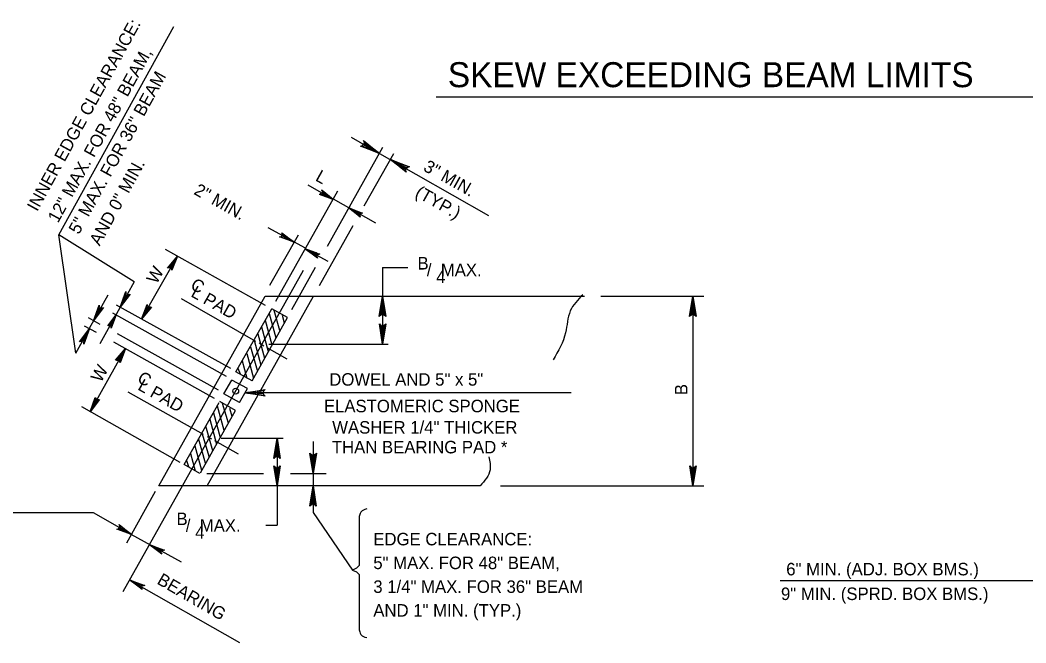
# Model space of a CAD drawing. Extents: x 639028 to 640031, y 298558 to 299746.
# Drawn here: x 639151 to 639392.4, y 298840.4 to 298989.8 of the extents above; entities that cross this region are included whole.
import ezdxf

# ---------------------------------------------------------------- set-up
doc = ezdxf.new("R2010")
doc.units = 0
doc.layers.add('1', color=7, linetype='Continuous')

msp = doc.modelspace()

# ---------------------------------------------------------------- linework, layer by layer
at = {"layer": '1'}
for p, q in [((639160.3, 298938.26), (639187.95, 298988.24)), ((639250.86, 298971.38), (639411.63, 298971.38)), ((639230.45, 298961.68), (639237.27, 298957.8)), ((639224.75, 298935.53), (639238.1, 298959.27)), ((639233.61, 298945.19), (639240.7, 298957.8)), ((639237.27, 298957.8), (639263.46, 298942.91)), ((639226.17, 298946.76), (639220.17, 298950.14)), ((639212.4, 298922.35), (639227.23, 298948.79)), ((639226.17, 298946.9), (639236.3, 298941.14)), ((639219.5, 298935.02), (639210.56, 298939.96)), ((639222.85, 298926.06), (639230.98, 298940.52)), ((639164.42, 298909.89), (639160.3, 298938.26)), ((639178.38, 298926.96), (639160.3, 298938.26)), ((639210.92, 298926.14), (639217.79, 298938.27)), ((639180.17, 298918.01), (639188.8, 298933.14)), ((639209.92, 298921.26), (639185.92, 298934.76)), ((639219.42, 298934.89), (639224.86, 298931.91)), ((639216.21, 298920.33), (639221.91, 298930.48)), ((639238, 298930.41), (639238, 298912.04)), ((639238, 298930.41), (639244.08, 298930.41)), ((639175.76, 298852.66), (639219.05, 298929.76)), ((639178.38, 298926.96), (639175.04, 298920.89)), ((639172.05, 298923.76), (639167.63, 298915.74)), ((639184.3, 298878.01), (639209.8, 298923.51)), ((639195.92, 298878.01), (639221.42, 298923.51)), ((639209.8, 298923.51), (639286.42, 298923.51)), ((639290.38, 298923.51), (639315.1, 298923.51)), ((639312.47, 298923.51), (639312.47, 298878.01)), ((639170.26, 298912.18), (639175.06, 298920.85)), ((639201.55, 298906.14), (639174.14, 298921.36)), ((639207.57, 298912.69), (639189.72, 298922.87)), ((639170.27, 298916.73), (639167.43, 298918.3)), ((639200.55, 298904.26), (639173.24, 298919.43)), ((639202.8, 298905.39), (639211.42, 298920.51)), ((639206.67, 298903.26), (639215.17, 298918.39)), ((639210.8, 298919.39), (639212.42, 298913.51)), ((639215.17, 298918.39), (639211.42, 298920.51)), ((639211.92, 298920.14), (639213.3, 298915.39)), ((639213.92, 298919.01), (639214.42, 298917.14)), ((639164.42, 298909.89), (639167.67, 298915.76)), ((639169.36, 298914.78), (639166.51, 298916.37)), ((639208.92, 298916.14), (639210.55, 298910.26)), ((639209.8, 298917.76), (639211.42, 298911.89)), ((639198.67, 298901.01), (639174.36, 298914.46)), ((639208.05, 298914.51), (639209.67, 298908.64)), ((639167.8, 298895.76), (639176.3, 298911.01)), ((639197.67, 298899.01), (639173.48, 298912.48)), ((639206.3, 298911.39), (639207.92, 298905.76)), ((639207.17, 298913.01), (639208.8, 298907.01)), ((639209.54, 298911.56), (639208.38, 298912.22)), ((639215.1, 298908.4), (639210.32, 298911.12)), ((639210.69, 298912.04), (639239.37, 298912.04)), ((639205.42, 298909.76), (639207.05, 298903.89)), ((639203.3, 298906.26), (639203.8, 298904.89)), ((639204.3, 298908.01), (639205.42, 298903.89)), ((639206.67, 298903.26), (639202.8, 298905.39)), ((639199.92, 298900.14), (639201.8, 298903.39)), ((639205.55, 298901.39), (639201.8, 298903.39)), ((639203.67, 298898.01), (639205.55, 298901.39)), ((639195.02, 298890.34), (639176.96, 298900.51)), ((639203.67, 298898.01), (639199.92, 298900.14)), ((639283.28, 298900.34), (639204.97, 298900.34)), ((639189.42, 298883.64), (639165.8, 298897.01)), ((639190.42, 298883.14), (639198.8, 298898.01)), ((639198.3, 298897.26), (639199.92, 298891.39)), ((639202.67, 298896.14), (639198.92, 298898.26)), ((639199.55, 298897.89), (639200.92, 298893.14)), ((639201.3, 298896.64), (639201.8, 298894.76)), ((639194.3, 298881.14), (639202.67, 298896.14)), ((639197.42, 298895.51), (639199.05, 298889.64)), ((639195.55, 298892.39), (639197.17, 298886.51)), ((639196.55, 298894.01), (639198.17, 298888.01)), ((639193.8, 298889.26), (639195.42, 298883.51)), ((639194.67, 298890.76), (639196.42, 298884.89)), ((639197.01, 298889.22), (639196.03, 298889.78)), ((639199.27, 298889.45), (639214.17, 298889.45)), ((639212.68, 298889.45), (639212.68, 298868.6)), ((639192.92, 298887.64), (639194.55, 298881.76)), ((639203.41, 298885.62), (639197.77, 298888.8)), ((639221.33, 298888.67), (639221.33, 298878.01)), ((639191.92, 298885.76), (639193.05, 298881.64)), ((639194.17, 298881.01), (639190.42, 298883.14)), ((639190.92, 298884.14), (639191.42, 298882.64)), ((639195.8, 298881.01), (639209.45, 298881.01)), ((639215.91, 298881.01), (639224.47, 298881.01)), ((639261.42, 298878.01), (639184.3, 298878.01)), ((639221.33, 298878.01), (639221.33, 298871.64)), ((639266.3, 298878.01), (639315.1, 298878.01)), ((639176.62, 298864.38), (639183.55, 298876.76)), ((639233.75, 298872.36), (639233.44, 298872.21)), ((639234.22, 298872.52), (639233.75, 298872.36)), ((639168.61, 298871.52), (639098.81, 298871.52)), ((639177.77, 298866.38), (639168.61, 298871.52)), ((639221.33, 298871.64), (639230.8, 298857.83)), ((639232.51, 298871.12), (639232.35, 298870.65)), ((639232.35, 298870.65), (639232.35, 298858.92)), ((639232.66, 298871.43), (639232.51, 298871.12)), ((639232.82, 298871.74), (639232.66, 298871.43)), ((639232.97, 298871.89), (639232.82, 298871.74)), ((639233.13, 298872.05), (639232.97, 298871.89)), ((639233.44, 298872.21), (639233.13, 298872.05)), ((639209.95, 298868.6), (639212.68, 298868.6)), ((639189.74, 298859.7), (639177.7, 298866.32)), ((639231.42, 298858.15), (639230.8, 298857.83)), ((639230.8, 298857.83), (639231.73, 298857.37)), ((639231.73, 298858.3), (639231.42, 298858.15)), ((639232.04, 298858.61), (639231.73, 298858.3)), ((639232.35, 298858.92), (639232.04, 298858.61)), ((639231.73, 298857.37), (639231.88, 298857.21)), ((639231.88, 298857.21), (639232.2, 298856.9)), ((639232.2, 298856.9), (639232.35, 298856.74)), ((639232.35, 298856.74), (639232.35, 298843.47)), ((639203.76, 298840.35), (639177.3, 298855.4)), ((639403.23, 298855.21), (639333.43, 298855.21)), ((639232.35, 298843.47), (639232.51, 298843.01)), ((639232.51, 298843.01), (639232.66, 298842.7)), ((639232.66, 298842.7), (639232.82, 298842.39)), ((639232.82, 298842.39), (639232.97, 298842.23)), ((639232.97, 298842.23), (639233.13, 298842.07)), ((639233.13, 298842.07), (639233.44, 298841.92)), ((639233.44, 298841.92), (639233.75, 298841.76)), ((639233.75, 298841.76), (639234.22, 298841.61))]:
    msp.add_line(p, q, dxfattribs=at)
for points in [[(639233.55, 298960.59), (639233.53, 298960.21), (639237.27, 298957.8), (639233.55, 298960.59), (639233.44, 298960.88), (639237.27, 298957.8), (639233.31, 298959.81), (639233, 298959.6), (639237.27, 298957.8), (639232.68, 298959.53), (639233, 298959.6)], [(639243.6, 298953.54), (639243.61, 298953.92), (639239.87, 298956.33), (639243.6, 298953.54), (639243.7, 298953.25), (639239.87, 298956.33), (639243.84, 298954.32), (639244.14, 298954.53), (639239.87, 298956.33), (639244.47, 298954.6), (639244.14, 298954.53)], [(639223.47, 298948.86), (639223.47, 298948.56), (639226.17, 298946.76), (639223.47, 298948.86), (639223.32, 298949.01), (639226.17, 298946.76), (639223.32, 298948.26), (639223.02, 298948.11), (639226.17, 298946.76), (639222.87, 298947.96), (639223.02, 298948.11)], [(639232.62, 298942.66), (639232.62, 298942.96), (639229.92, 298944.76), (639232.62, 298942.66), (639232.62, 298942.51), (639229.92, 298944.76), (639232.77, 298943.26), (639232.92, 298943.41), (639229.92, 298944.76), (639233.22, 298943.41), (639232.92, 298943.41)], [(639213.92, 298938.51), (639213.92, 298938.26), (639216.8, 298936.51), (639213.92, 298938.51), (639213.8, 298938.76), (639216.8, 298936.51), (639213.8, 298938.01), (639213.55, 298937.76), (639216.8, 298936.51), (639213.3, 298937.76), (639213.55, 298937.76)], [(639186.67, 298930.39), (639186.92, 298930.39), (639188.8, 298933.14), (639186.67, 298930.39), (639186.42, 298930.26), (639188.8, 298933.14), (639187.3, 298930.14), (639187.42, 298930.01), (639188.8, 298933.14), (639187.42, 298929.76), (639187.42, 298930.01)], [(639221.67, 298933.26), (639221.67, 298933.51), (639219.42, 298934.89), (639221.67, 298933.26), (639221.8, 298933.14), (639219.42, 298934.89), (639221.8, 298933.76), (639222.05, 298933.89), (639219.42, 298934.89), (639222.17, 298933.89), (639222.05, 298933.89)], [(639222.3, 298932.89), (639222.3, 298933.14), (639219.42, 298934.89), (639222.3, 298932.89), (639222.42, 298932.64), (639219.42, 298934.89), (639222.42, 298933.51), (639222.67, 298933.64), (639219.42, 298934.89), (639222.92, 298933.64), (639222.67, 298933.64)], [(639177.29, 298923.89), (639176.99, 298923.89), (639175.04, 298920.89), (639177.29, 298923.89), (639177.44, 298924.04), (639175.04, 298920.89), (639176.54, 298924.04), (639176.39, 298924.34), (639175.04, 298920.89), (639176.39, 298924.64), (639176.39, 298924.34)], [(639237.42, 298918.9), (639237.75, 298919.07), (639238, 298923.51), (639237.42, 298918.9), (639237.22, 298918.66), (639238, 298923.51), (639238.22, 298919.07), (639238.55, 298918.91), (639238, 298923.51), (639238.77, 298918.66), (639238.55, 298918.91)], [(639311.89, 298918.9), (639312.22, 298919.07), (639312.47, 298923.51), (639311.89, 298918.9), (639311.69, 298918.66), (639312.47, 298923.51), (639312.69, 298919.07), (639313.02, 298918.91), (639312.47, 298923.51), (639313.24, 298918.66), (639313.02, 298918.91)], [(639170.92, 298920.64), (639170.62, 298920.64), (639168.67, 298917.64), (639170.92, 298920.64), (639171.07, 298920.79), (639168.67, 298917.64), (639170.17, 298920.79), (639170.02, 298921.09), (639168.67, 298917.64), (639170.02, 298921.39), (639170.02, 298921.09)], [(639182.3, 298920.89), (639182.05, 298920.89), (639180.17, 298918.01), (639182.3, 298920.89), (639182.55, 298920.89), (639180.17, 298918.01), (639181.67, 298921.01), (639181.55, 298921.26), (639180.17, 298918.01), (639181.55, 298921.51), (639181.55, 298921.26)], [(639172.29, 298916.52), (639172.54, 298916.52), (639174.04, 298919.02), (639172.29, 298916.52), (639172.04, 298916.39), (639174.04, 298919.02), (639172.79, 298916.39), (639172.91, 298916.14), (639174.04, 298919.02), (639172.91, 298915.89), (639172.91, 298916.14)], [(639165.57, 298912.76), (639165.87, 298912.76), (639167.67, 298915.76), (639165.57, 298912.76), (639165.27, 298912.61), (639167.67, 298915.76), (639166.17, 298912.61), (639166.32, 298912.31), (639167.67, 298915.76), (639166.32, 298912.01), (639166.32, 298912.31)], [(639238.58, 298916.65), (639238.25, 298916.48), (639238, 298912.04), (639238.58, 298916.65), (639238.78, 298916.89), (639238, 298912.04), (639237.78, 298916.48), (639237.45, 298916.64), (639238, 298912.04), (639237.23, 298916.89), (639237.45, 298916.64)], [(639174.17, 298908.14), (639174.55, 298908.14), (639176.3, 298911.01), (639174.17, 298908.14), (639173.92, 298908.14), (639176.3, 298911.01), (639174.8, 298908.01), (639174.92, 298907.76), (639176.3, 298911.01), (639175.05, 298907.51), (639174.92, 298907.76)], [(639169.92, 298898.64), (639169.55, 298898.64), (639167.8, 298895.76), (639169.92, 298898.64), (639170.05, 298898.76), (639167.8, 298895.76), (639169.3, 298898.76), (639169.17, 298899.01), (639167.8, 298895.76), (639169.05, 298899.26), (639169.17, 298899.01)], [(639209.58, 298899.76), (639209.41, 298900.1), (639204.97, 298900.34), (639209.58, 298899.76), (639209.82, 298899.56), (639204.97, 298900.34), (639209.41, 298900.56), (639209.57, 298900.89), (639204.97, 298900.34), (639209.82, 298901.11), (639209.57, 298900.89)], [(639212.1, 298884.84), (639212.44, 298885.01), (639212.68, 298889.45), (639212.1, 298884.84), (639211.9, 298884.6), (639212.68, 298889.45), (639212.9, 298885.01), (639213.23, 298884.85), (639212.68, 298889.45), (639213.45, 298884.6), (639213.23, 298884.85)], [(639221.91, 298885.62), (639221.58, 298885.45), (639221.33, 298881.01), (639221.91, 298885.62), (639222.11, 298885.86), (639221.33, 298881.01), (639221.11, 298885.45), (639220.78, 298885.61), (639221.33, 298881.01), (639220.56, 298885.86), (639220.78, 298885.61)], [(639213.26, 298882.62), (639212.93, 298882.45), (639212.68, 298878.01), (639213.26, 298882.62), (639213.46, 298882.86), (639212.68, 298878.01), (639212.46, 298882.45), (639212.13, 298882.61), (639212.68, 298878.01), (639211.91, 298882.86), (639212.13, 298882.61)], [(639313.05, 298882.62), (639312.71, 298882.45), (639312.47, 298878.01), (639313.05, 298882.62), (639313.25, 298882.86), (639312.47, 298878.01), (639312.25, 298882.45), (639311.92, 298882.61), (639312.47, 298878.01), (639311.7, 298882.86), (639311.92, 298882.61)], [(639220.75, 298873.4), (639221.09, 298873.57), (639221.33, 298878.01), (639220.75, 298873.4), (639220.55, 298873.16), (639221.33, 298878.01), (639221.55, 298873.57), (639221.88, 298873.41), (639221.33, 298878.01), (639222.1, 298873.16), (639221.88, 298873.41)], [(639174.9, 298868.5), (639174.9, 298868.13), (639177.77, 298866.38), (639174.9, 298868.5), (639174.77, 298868.75), (639177.77, 298866.38), (639174.77, 298867.88), (639174.52, 298867.75), (639177.77, 298866.38), (639174.27, 298867.63), (639174.52, 298867.75)], [(639184.9, 298861.88), (639184.9, 298862.13), (639182.15, 298863.88), (639184.9, 298861.88), (639185.02, 298861.63), (639182.15, 298863.88), (639185.15, 298862.5), (639185.4, 298862.63), (639182.15, 298863.88), (639185.65, 298862.63), (639185.4, 298862.63)], [(639180.17, 298853.4), (639180.17, 298853.65), (639177.42, 298855.4), (639180.17, 298853.4), (639180.3, 298853.15), (639177.42, 298855.4), (639180.42, 298854.02), (639180.67, 298854.15), (639177.42, 298855.4), (639180.92, 298854.15), (639180.67, 298854.15)]]:
    msp.add_lwpolyline(points, dxfattribs=at)
msp.add_circle((639202.76, 298900.75), 0.704, dxfattribs=at)
for points in [[(639286.05, 298923.89), (639283.05, 298920.01), (639281.92, 298914.76), (639278.96, 298908.28)], [(639263.52, 298885.01), (639263.8, 298881.89), (639261.42, 298878.01)]]:
    msp.add_spline(points, degree=3, dxfattribs=at)

# ---------------------------------------------------------------- texts
for s, rotation, p in [('INNER EDGE CLEARANCE:', 61.1443, (639155.12, 298943.67)), ('12" MAX. FOR 48" BEAM,', 61.1443, (639160.11, 298940.92)), ('5" MAX. FOR 36" BEAM', 61.1443, (639165.11, 298938.17)), ('AND 0" MIN.', 61.1443, (639170.1, 298935.42)), ('3" MIN.', 330.7111, (639247.56, 298953.77)), ('L', 330.7111, (639221.67, 298951.39)), ('2" MIN.', 330.7111, (639192.5, 298948.12)), ('(TYP.)', 330.7111, (639245.59, 298947.59)), ('W', 60.7111, (639183.78, 298926.24)), ('L PAD', 330.6193, (639191.79, 298923.58)), ('C', 330.6193, (639191.67, 298925.45)), ('W', 60.7111, (639170.41, 298902.63)), ('C', 330.6193, (639178.92, 298903.09)), ('L PAD', 330.6193, (639179.04, 298901.22)), ('B', 90, (639311.17, 298899.79)), ('  BEARING', 329.9781, (639181.73, 298855.77))]:
    msp.add_text(s, height=3, rotation=rotation, dxfattribs=at).set_placement(p)
for s, height, p in [('SKEW EXCEEDING BEAM LIMITS', 6, (639253.66, 298973.67)), ('B', 3, (639246.39, 298929.93)), ('/  MAX.', 3, (639248.63, 298928.33)), ('4', 3, (639250.86, 298926.67)), ('DOWEL AND 5" x 5"', 3, (639225.21, 298902.06)), (' ELASTOMERIC SPONGE', 3, (639222.81, 298895.68)), ('WASHER 1/4" THICKER', 3, (639225.92, 298890.56)), ('THAN BEARING PAD *', 3, (639225.83, 298885.82)), ('B', 3, (639188.55, 298868.62)), ('/  MAX.', 3, (639190.79, 298867.02)), ('4', 3, (639193.02, 298865.36)), ('EDGE CLEARANCE:', 3, (639235.78, 298863.75)), ('5" MAX. FOR 48" BEAM,', 3, (639235.78, 298858.05)), ('6" MIN. (ADJ. BOX BMS.)', 3, (639334.87, 298856.55)), ('3 1/4" MAX. FOR 36" BEAM', 3, (639235.78, 298852.35)), ('9" MIN. (SPRD. BOX BMS.)', 3, (639333.61, 298850.63)), ('AND 1" MIN. (TYP.)', 3, (639235.78, 298846.65))]:
    msp.add_text(s, height=height, dxfattribs=at).set_placement(p)

doc.saveas('drawing.dxf')
